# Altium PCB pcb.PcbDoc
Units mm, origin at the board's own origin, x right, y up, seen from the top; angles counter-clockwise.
Board outline 66.48 x 77.37 mm, 2 copper layers (Top Layer, Bottom Layer); 46 components, 42 nets, 221 pads, 768 vias.
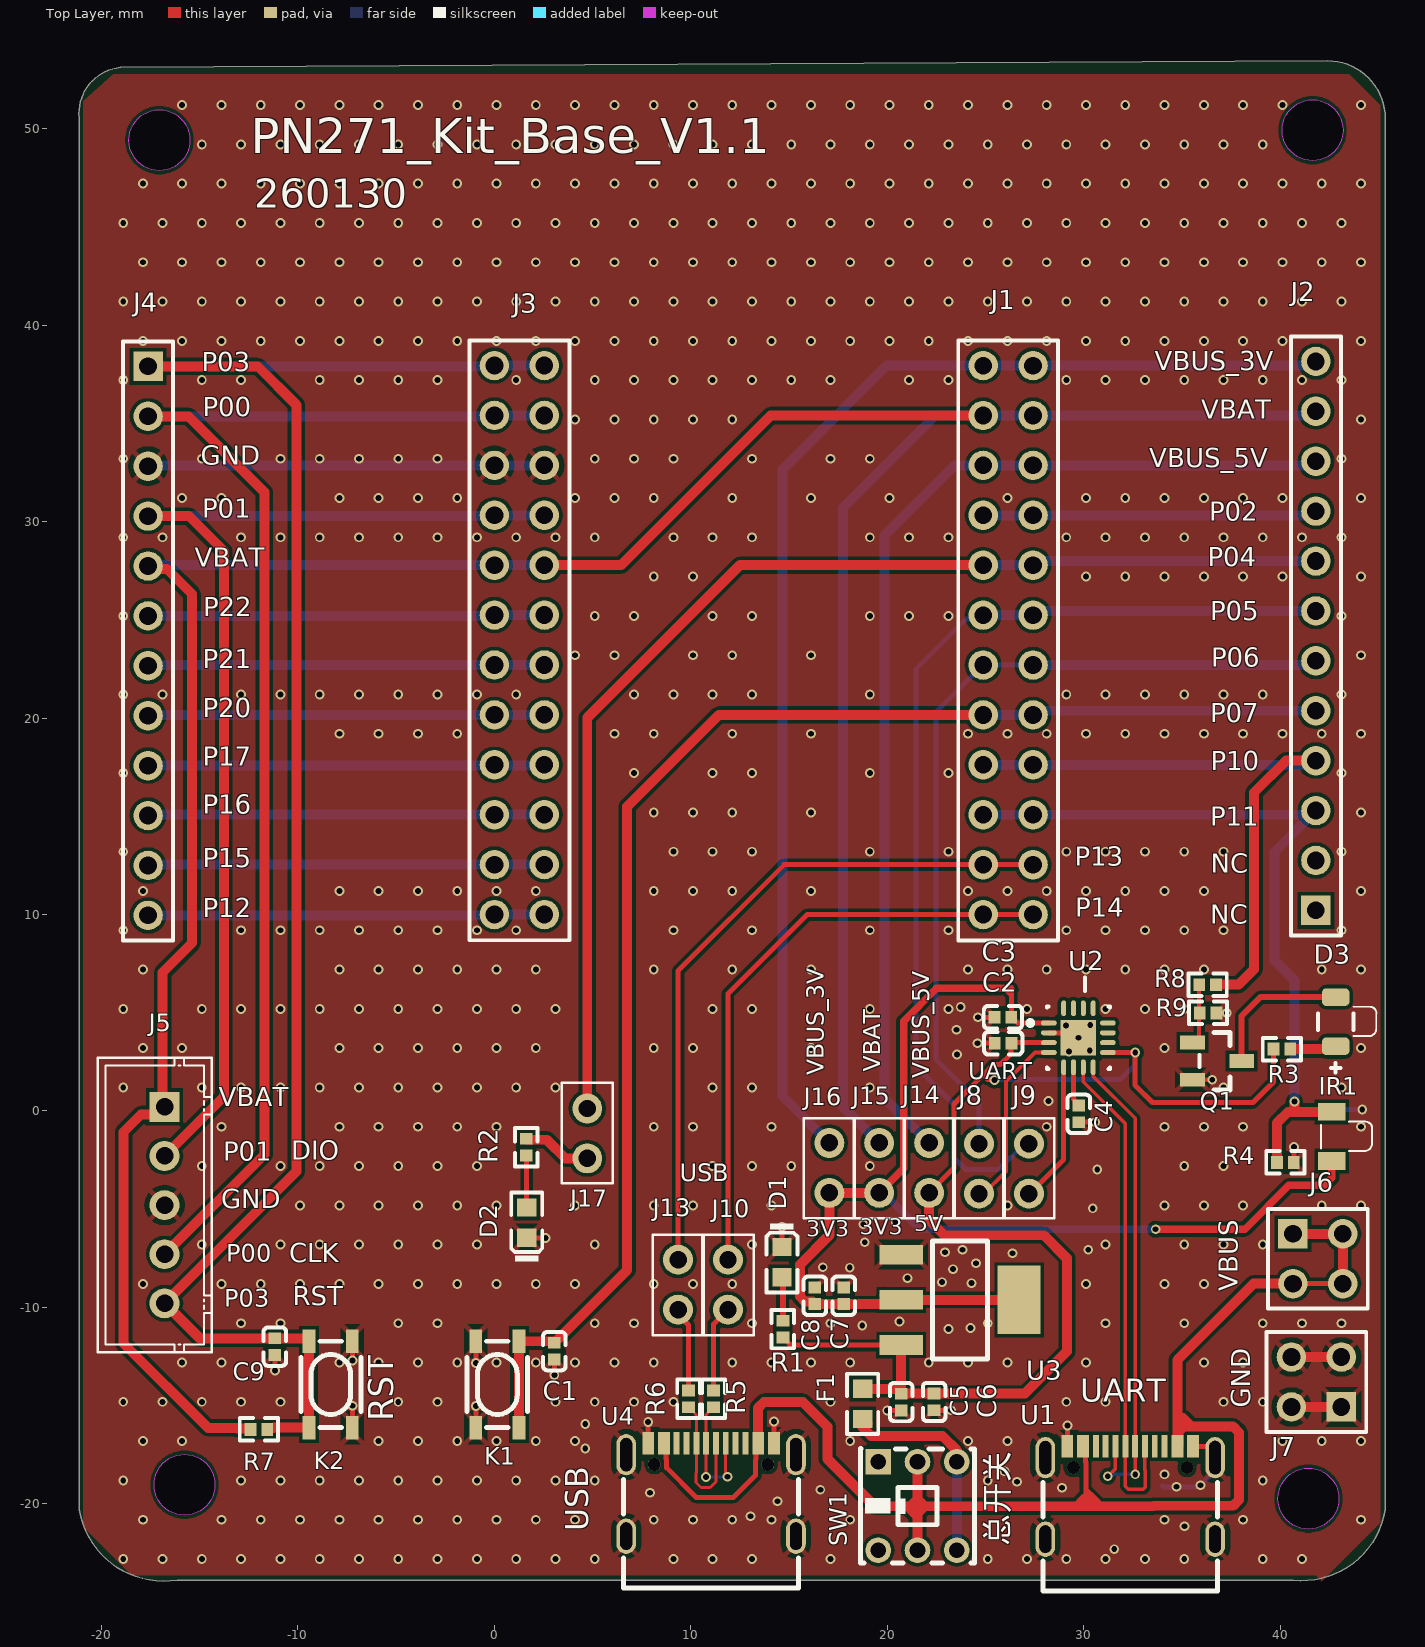
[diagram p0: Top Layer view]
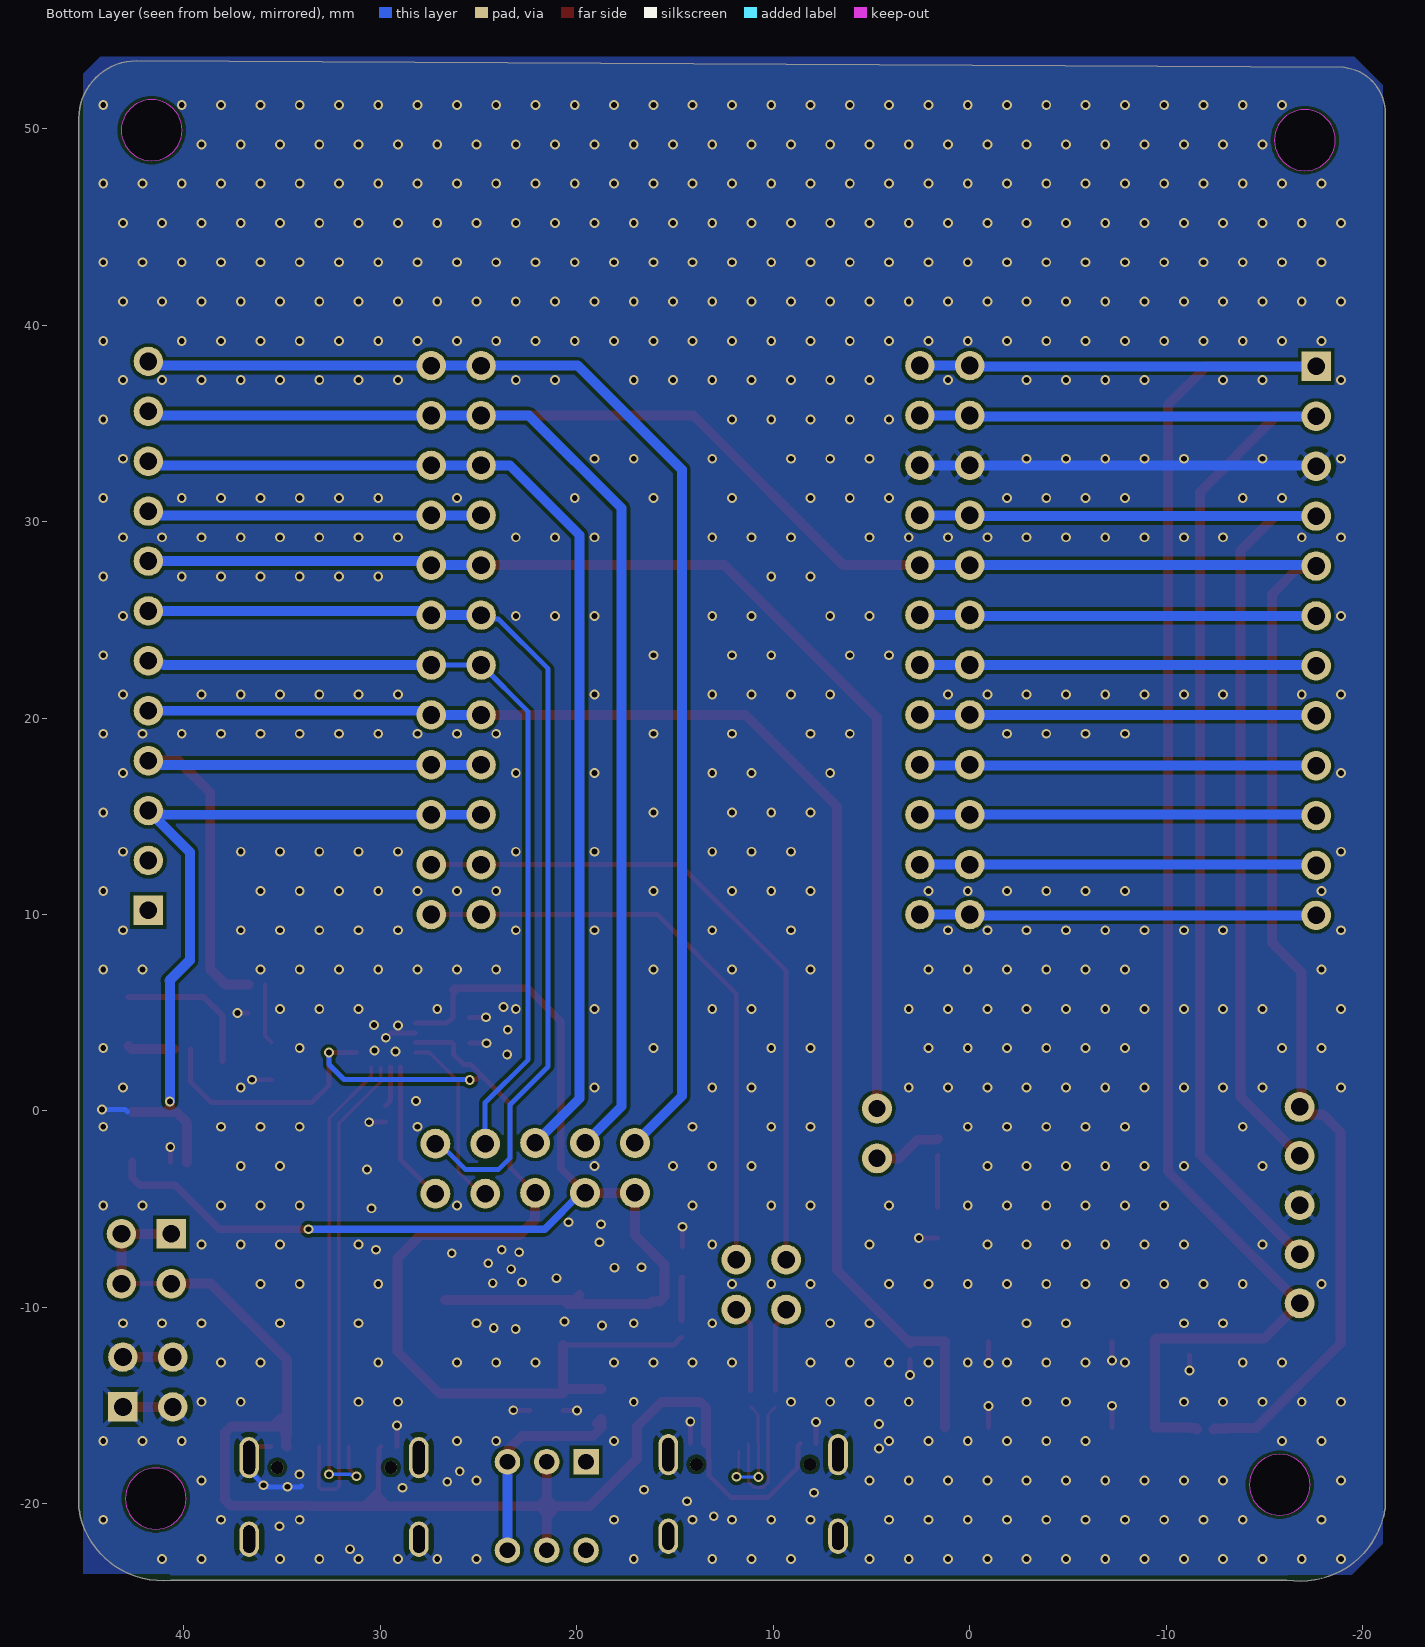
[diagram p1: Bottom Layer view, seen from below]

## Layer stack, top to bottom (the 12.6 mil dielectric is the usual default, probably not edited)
Top Solder: solder mask 0.0102, Solder Resist, Dk 3.5
Top Layer: signal copper 0.0356
Dielectric 1: dielectric 0.32, FR-4, Dk 4.8
Bottom Layer: signal copper 0.0356
Bottom Solder: solder mask 0.0102, Solder Resist, Dk 3.5

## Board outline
-21.13,-20.285 cw(c-20.879,-20.244) -21.133,-20.243 -21.133,-19.254 -21.133,50.559 cw(c-18.809,50.787) -19.051,53.11 cw(c-19.025,52.857) -19.026,53.112 42.417,53.442 cw(c42.418,53.188) 42.418,53.442 cw(c42.418,50.521) 45.339,50.521 cw(c45.085,50.521) 45.339,50.519 45.339,-19.122 45.339,-20.244 cw(c45.085,-20.244) 45.336,-20.283 cw(c41.11,-19.621) 40.667,-23.876 -16.134,-23.876 cw(c-16.827,-19.571)
cut-out: 41.43,-21.279 cw(c41.43,-19.729) 39.88,-19.729 cw(c41.43,-19.729) 41.43,-18.179 cw(c41.43,-19.729) 42.98,-19.729 cw(c41.43,-19.729)
cut-out: 41.64,48.37 cw(c41.64,49.92) 40.09,49.92 cw(c41.64,49.92) 41.64,51.47 cw(c41.64,49.92) 43.19,49.92 cw(c41.64,49.92)
cut-out: -17.053,47.862 cw(c-17.053,49.412) -18.603,49.412 cw(c-17.053,49.412) -17.053,50.962 cw(c-17.053,49.412) -15.503,49.412 cw(c-17.053,49.412)
cut-out: -15.774,-20.575 cw(c-15.774,-19.025) -17.324,-19.025 cw(c-15.774,-19.025) -15.774,-17.475 cw(c-15.774,-19.025) -14.224,-19.025 cw(c-15.774,-19.025)

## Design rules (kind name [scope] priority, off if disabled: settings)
Clearance [All] p1: gap=0.173
HoleSize [All] p1: absolutevalues=TRUE maxlimit=3.81 minlimit=0.025 maxpercent=80.000 minpercent=20.000
MinimumSolderMaskSliver [All] p1: minsoldermaskwidth=0.025
PolygonConnect PolygonConnect_1 [IsVia vs IsPoly] p1: connectstyle=Direct reliefconductorwidth=0.254 reliefentries=4 polygonreliefangle="90 Angle" airgapwidth=0.254
PolygonConnect [All] p2: connectstyle=Relief reliefconductorwidth=0.254 reliefentries=4 polygonreliefangle="45 Angle" airgapwidth=0.254
RoutingVias [All] p1: holewidth=0.3 width=0.5 viastyle="Through Hole" minholewidth=0.3 minwidth=0.5 maxholewidth=0.3 maxwidth=0.5
SilkToSilkClearance [All] p1 off: silktosilkclearance=0.254
SilkToSolderMaskClearance [IsPad] p1 off: minsilkscreentomaskgap=0.254 clearancetoexposedcopper=TRUE
SolderMaskExpansion SolderMaskExpansion_1 [IsVia] p1: expansion=0.102
SolderMaskExpansion [All] p2: expansion=0.102
Width [All] p1: maxlimit=1.27 minlimit=0.152 preferedwidth=0.203 minimp=50.000000 maximp=50.000000 favimp=50.000000
26 further rules are at their usual default settings.

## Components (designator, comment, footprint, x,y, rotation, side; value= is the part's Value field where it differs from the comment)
C1 "100nF / NC" 0402_C 3.048,-12.224 r90 top
C2 "100nF" 0402_C 25.894,3.449 r180 top
C3 "4.7uF" 0402_C 25.88,4.77 r180 top
C4 "100nF" 0402_C 29.743,-0.146 r270 top
C5 "100nF" 0402_C 20.701,-14.815 r90 top
C6 "10uF" 0402_C 22.377,-14.808 r90 top
C7 "100nF" 0402_C 17.78,-9.405 r270 top
C8 "10uF" 0402_C 16.307,-9.405 r270 top
C9 "100nF / NC" 0402_C -11.176,-11.996 r90 top
D1 "红灯 0603" 0603_LED_S1 14.63,-7.696 r270 top
D2 "绿灯 0603" 0603_LED_S1 1.645,-5.686 r90 top
D3 "IR26-51C/L110/TR8" FP-IR26-51C-L110-TR8-MFG 42.816,4.547 r90 top
F1 "" 0603_R 18.745,-14.91 r90 top
IR1 "PT26-51B/TR8" OPTO-SMD_PT26-51B-TR8 42.621,-1.295 r270 top
J1 "Header 2x12" "Header 2X12" 24.875,37.938 r270 top locked
J2 "nc" HDR1X12 41.808,10.211 r90 top
J3 "Header 2x12" "Header 2X12" 0,37.94 r270 top locked
J4 "nc" HDR1X12 -17.628,37.897 r270 top
J5 "SWD" "XH 1x5" -16.789,0.21 r270 top
J6 "Header 2X2" HDR2X2 40.64,-6.248 r270 top
J7 "Header 2X2" HDR2X2 43.104,-15.062 r90 top
J8 "Header 2" "Header 1x2" 24.663,-1.666 r0 top
J9 "Header 2" "Header 1x2" 27.203,-1.666 r0 top
J10 "Header 2" "Header 1x2" 11.887,-10.109 r180 top
J13 "Header 2" "Header 1x2" 9.347,-10.109 r180 top
J14 "Header 2" "Header 1x2" 22.123,-4.166 r180 top
J15 "Header 2" "Header 1x2" 19.583,-4.166 r180 top
J16 "Header 2" "Header 1x2" 17.043,-4.166 r180 top
J17 "Header 2" "Header 1x2" 4.724,0.127 r0 top
K1 "K2-1808GN-A4SW-04" KEY-SMD_4P-L4.2-W3.2-P2.20-LS5.1-TL 0.152,-13.919 r270 top
K2 "K2-1808GN-A4SW-04" KEY-SMD_4P-L4.2-W3.2-P2.20-LS5.1-TL -8.331,-13.919 r90 top
Q1 "SS8050 Y1" SOT-23(SOT-23-3) 36.779,2.54 r180 top
R1 "1KΩ" 0402_R 14.681,-11.1 r90 top
R2 "1KΩ" 0402_R 1.619,-1.843 r270 top
R3 "100Ω" 0402_R 40.081,3.15 r180 top
R4 "300Ω" 0402_R 40.259,-2.616 r180 top
R5 "0Ω" 0402_R 11.151,-14.649 r270 top
R6 "0Ω" 0402_R 9.881,-14.649 r270 top
R7 "NC" 0402_R -11.989,-16.205 r180 top
R8 "300Ω" 0402_R 36.297,6.426 r180 top
R9 "10KΩ" 0402_R 36.32,4.994 r180 top
SW1 "K8-5851E-L1" SW-TH_6P-L5.8-W5.8-P2.00-LS4.5-TL_K8-5851E-L1 21.533,-20.106 r0 top
U1 "USB_Type-C(Seat-16P)" USB-C-SMD_TYPE-C16PIN 32.36,-19.431 r0 top
U2 "CH343P" QFN16 29.723,3.728 r0 top
U3 "AMS1117-3.3" SOT-223 23.701,-9.613 r180 top
U4 "USB_Type-C(Seat-16P)" USB-C-SMD_TYPE-C16PIN 11.026,-19.279 r0 top

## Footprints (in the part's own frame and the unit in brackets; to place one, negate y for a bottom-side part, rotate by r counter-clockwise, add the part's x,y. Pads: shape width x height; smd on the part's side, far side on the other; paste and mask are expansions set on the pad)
0402_C [mm]
  rect 0.6x0.65 smd mask+0.051: 1(-0.425,0) 2(0.425,0)
  silkscreen extent -0.97,-0.58 0.97,0.58, body extent -0.48,-0.3 0.52,0.3, height 0.2
0402_R [mm]
  rect 0.6x0.65 smd mask+0.051: 1(-0.425,0) 2(0.425,0)
  silkscreen extent -0.97,-0.58 0.97,0.58, body extent -0.57,-0.27 0.58,0.28, height 0.41
0603_LED_S1 [mm]
  rect 0.93x0.98 smd: A(0.77,0) K(-0.77,0)
  silkscreen extent -1.97,-0.79 1.54,0.79, body extent -0.8,-0.4 0.8,0.4, height 0.6
0603_R [mm]
  rect 0.93x0.98 smd: 1(-0.77,0) 2(0.77,0)
  silkscreen extent -1.53,-0.79 1.54,0.79, body extent -0.85,-0.4 0.85,0.4, height 0.56
FP-IR26-51C-L110-TR8-MFG [mm]
  rrect50% 0.9x1.4 smd paste+0 mask+0: 1(-1.25,0) 2(1.25,0)
  silkscreen extent -2.6,-0.9 0.43,0.9, body extent -1.8,-1 1.8,1, height 0.25
HDR1X12 [mm] "Connector; Header; 12 Position"
  rect 1.5x1.5 hole 0.9: 1(0,0)
  round 1.5 hole 0.9: 2(2.54,0) 3(5.08,0) 4(7.62,0) 5(10.16,0) 6(12.7,0) 7(15.24,0) 8(17.78,0) 9(20.32,0) 10(22.86,0) 11(25.4,0) 12(27.94,0)
  silkscreen extent -1.27,-1.27 29.21,1.27
HDR2X2 [mm] "Connector; Header; 2x2 Position"
  rect 1.5x1.5 hole 0.9: 1(0,0)
  round 1.5 hole 0.9: 2(0,2.54) 3(2.54,0) 4(2.54,2.54)
  silkscreen extent -1.27,-1.27 3.81,3.81
"Header 1x2" [mil] "Header 1x2,2.54mm"
  round 60 hole 35: 1(0,0) 2(0,-100)
  silkscreen extent -51,-150 51,51, body extent -50,-150 50,50, height 335
"Header 2X12" [mm] "Connector; Header; 12x2 Position"
  round 1.5 hole 0.9: 1(0,0) 2(0,2.54) 3(2.54,0) 4(2.54,2.54) 5(5.08,0) 6(5.08,2.54) 7(7.62,0) 8(7.62,2.54) 9(10.16,0) 10(10.16,2.54) 11(12.7,0) 12(12.7,2.54) 13(15.24,0) 14(15.24,2.54) 15(17.78,0) 16(17.78,2.54) 17(20.32,0) 18(20.32,2.54) 19(22.86,0) 20(22.86,2.54) 21(25.4,0) 22(25.4,2.54) 23(27.94,0) 24(27.94,2.54)
  silkscreen extent -1.27,-1.27 29.25,3.81, body extent -1.27,-1.27 29.21,3.81, height 8.5
KEY-SMD_4P-L4.2-W3.2-P2.20-LS5.1-TL [mm]
  rect 1.2x0.65 smd: 1(-2.2,1.1) 2(2.2,1.1) 3(-2.2,-1.1) 4(2.2,-1.1)
  silkscreen extent -2.2,-1.55 2.2,1.52
OPTO-SMD_PT26-51B-TR8 [mm]
  rect 0.9x1.4 smd paste+0 mask+0.05: 1(-1.25,0) 2(1.25,0)
  silkscreen extent -0.76,-0.55 0.74,2.05
QFN16 [mm]
  oval 0.8x0.25 smd: 1(-1.5,0.75) 2(-1.5,0.25) 3(-1.5,-0.25) 4(-1.5,-0.75) 9(1.5,-0.75) 10(1.5,-0.25) 11(1.5,0.25) 12(1.5,0.75)
  oval 0.25x0.8 smd: 5(-0.75,-1.5) 6(-0.25,-1.5) 7(0.25,-1.5) 8(0.75,-1.5) 13(0.75,1.5) 14(0.25,1.5) 15(-0.25,1.5) 16(-0.75,1.5)
  rect 1.8x1.8 smd: 17(0,0)
  silkscreen extent -2.57,-1.6 1.6,1.6, body extent -1.58,-1.58 1.58,1.58, height 1
SOT-23(SOT-23-3) [mm]
  rect 1.25x0.7 smd: 1(1.25,-0.95) 2(1.25,0.95) 3(-1.25,0)
  silkscreen extent -0.65,-1.46 0.9,1.46, body extent -1.5,-1.5 1.5,1.5, height 1.3
SOT-223 [mm]
  rect 2.2x1 smd: 1(3,-2.3) 2(3,0) 3(3,2.3)
  rect 2.2x3.5 smd: 2(-3,0)
  silkscreen extent -1.4,-3 1.4,3, body extent -3.49,-3.24 3.49,3.24, height 1.64
SW-TH_6P-L5.8-W5.8-P2.00-LS4.5-TL_K8-5851E-L1 [mm]
  rect 1.3x1.3 hole 0.8 paste+0 mask+0.05: 1(-2,2.25)
  round 1.3 hole 0.8 paste+0 mask+0.05: 2(0,2.25) 3(2,2.25) 4(-2,-2.25) 5(0,-2.25) 6(2,-2.25)
  silkscreen extent -2.9,-2.9 2.9,2.92
USB-C-SMD_TYPE-C16PIN [mm]
  oval 1x2.1 hole 0.6 slot 1.7 at 90 deg: 1(-4.32,1.787) 2(4.32,1.787)
  oval 1x1.8 hole 0.6 slot 1.4 at 90 deg: 3(-4.32,-2.362) 4(4.32,-2.362)
  rect 0.6x1.15 smd: A1/B12(-3.2,2.362) A4/B9(-2.4,2.362) A9/B4(2.4,2.362) A12/B1(3.2,2.362)
  rect 0.3x1.15 smd: A5(-1.25,2.362) A6(-0.25,2.362) A7(0.25,2.362) A8(-1.75,2.362) B5(1.75,2.362) B6(0.75,2.362) B7(-0.75,2.362) B8(1.25,2.362)
  round 0.65 hole 0.65 unplated: ""(-2.89,1.288) ""(2.89,1.288)
  silkscreen extent -4.45,-5 4.45,0.52, body extent -4.47,-5 4.47,2.9, height 3.2
"XH 1x5" [mil] "XH 1x5,2.5mm"
  rect 60x60 / inner round 60 / far side round 60 hole 35: 1(0,0)
  round 60 hole 35: 2(98.43,0) 3(196.85,0) 4(295.28,0) 5(393.7,0)
  silkscreen extent -98,-134 492,94

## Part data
C1 C2 C4 C5 C7 C9: library part "0402 100nF (104) 10% 16V", "贴片电容"
C3: library part "0402 4.7uF (475) 20% 10V", "贴片电容"
C6 C8: library part "0402 10uF (106) 20% 6.3V", "贴片电容"
D1: library part "0603 红灯", "发光二极管"
D2: library part "0603 绿灯", "发光二极管"
D3: "EMITTER IR 940NM 65MA SMD"
F1: library part Res1, "Resistor"
J1 J3: "Header 2x11,2.54mm"
J2 J4: library part "Header 12", "Header, 12-Pin"
J5: library part "Header 1x5", "Header 1x5,2.54mm"
J6 J7: "Header, 2-Pin, Dual row"
J8 J9 J10 J13 J14 J15 J16 J17: library part SW-SPST, "Header, 2-Pin"
Q1: library part "SOT-23 SS8050 Y1", "三极管"
R1 R2 R7: library part "0402 1KΩ (1001) 1%", "贴片电阻"
R3 R4 R8: library part "0402 300Ω (3000) 1%", "贴片电阻"
R5 R6: library part "0402 0Ω (0R0) 1%", "贴片电阻"
R9: library part "0402 10KΩ (1002) 1%", "贴片电阻"
U2: "USB 转高速串口芯片"
U3: library part "SOT-223 AMS1117-3.3", "低压差线性稳压(LDO)"

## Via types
v1: diameter 0.5, hole 0.3, Top Layer to Bottom Layer, tented both sides, 768 vias

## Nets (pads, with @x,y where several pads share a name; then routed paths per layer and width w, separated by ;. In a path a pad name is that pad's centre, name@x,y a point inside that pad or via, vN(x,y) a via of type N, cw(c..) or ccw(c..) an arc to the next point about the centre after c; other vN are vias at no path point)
3V3_1: C3.1 C7.2 C8.2 IR1.2 J15.1 J16.1 U2.1 U3.2 | length 65.9
  Top Layer w0.254: 25.806,6.243 25.955,6.243 26.305,5.893 ; 26.305,6.181 26.305,5.893 ; U2.1 26.627,4.478 26.534,4.572 26.478,4.572 26.305,4.745 C3.1 26.305,5.893
  Top Layer w0.381: J15.1 20.828,-2.921 20.828,4.572 22.499,6.243 25.806,6.243 ; 25.955,6.243 26.244,6.243 26.305,6.181 ; v1(33.655,-6.02) 38.202,-6.02 40.437,-3.785 42.24,-3.785 42.621,-3.404 IR1.2
  Top Layer w0.508: J15.1 J16.1 17.043,-6.325 15.547,-7.821 15.547,-9.449 15.805,-9.707 16.184,-9.707 C8.2 C7.2 20.484,-9.83 U3.2@20.701,-9.613 ; U3.2@19.855,-9.367 20.101,-9.613 U3.2@20.701,-9.613 ; U3.2@26.701,-9.613 U3.2@20.701,-9.613
  Bottom Layer w0.381: J15.1 19.79,-4.166 21.644,-6.02 v1(33.655,-6.02)
5V_1: C2.1 C5.2 C6.2 F1.2 J14.1 R1.1 R3.2 U2.3 U2.9 U3.3 | length 66.5
  Top Layer w0.254: R1.1 14.706,-11.525 14.879,-11.698 14.879,-11.723 15.069,-11.913 U3.3 ; J14.1 23.393,-2.896 23.393,0.356 24.879,1.841 ; v1(25.451,1.575) 25.411,1.615 25.106,1.615 24.879,1.841 ; U2.3 26.348,3.478 C2.1 26.285,3.415 26.285,2.892 25.756,2.362 25.4,2.362 24.879,1.841 ; U2.9 32.607,2.978 32.607,1.315 33.491,0.432 38.608,0.432 39.656,1.48 R3.2
  Top Layer w0.508: F1.2 C5.2@20.451,-14.14 ; U3.3 C5.2 20.708,-14.383 C6.2 26.993,-14.383 29.134,-12.243 29.134,-7.493 27.965,-6.325 22.911,-6.325 22.708,-6.122 22.123,-5.537 J14.1
  Bottom Layer w0.254: v1(25.451,1.575) 25.476,1.6 31.852,1.6 32.614,2.362 v1(32.614,2.972)
DM_1: R6.2 U4.A7 U4.B7 | length 7.2
  Top Layer w0.152: R6.2 9.906,-15.074 10.129,-15.298 10.129,-15.323 10.276,-15.469 U4.B7 10.276,-18.41 10.261,-18.424 10.261,-18.912 10.26,-18.913 10.508,-19.16 10.979,-19.16 11.276,-18.864 U4.A7
DP_1: R5.2 U4.A6 U4.B6 | length 6.2
  Top Layer w0.152: v1(10.76,-18.631) U4.A6@10.76,-16.916 ; U4.A6 10.776,-15.449 10.902,-15.323 10.902,-15.298 11.126,-15.074 R5.2 ; U4.B6@11.76,-17.323 11.76,-18.416 11.868,-18.524 v1(11.868,-18.618)
  Bottom Layer w0.152: v1(10.76,-18.631) 11.855,-18.631 v1(11.868,-18.618)
GND: C1.1 C2.2 C3.2 C4.2 C5.1 C6.1 C7.1 C8.1 C9.1 D1.K D2.K J3.5 J3.6 J4.3 J5.3 J7.1 J7.2 J7.3 J7.4 K1.3 K1.4 K2.3 K2.4 Q1.2 R4.1 R9.1 U1.1 U1.2 U1.3 U1.4 U1.A1/B12 U1.A12/B1 U2.2 U2.17 U3.1 U4.1 U4.2 U4.3 U4.4 U4.A1/B12 U4.A12/B1 | length 51
  Top Layer w0.254: v1(-11.176,-13.208) C9.1 ; K2.3 v1(-7.231,-15.004) ; v1(-7.231,-12.692) K2.4 ; K1.4 v1(-0.948,-15.019) ; v1(-0.948,-12.819) K1.3 ; D2.K v1(2.596,-6.456) ; v1(3.048,-13.437) C1.1 ; U4.A1/B12 v1(7.826,-15.822) ; U4.A12/B1 v1(14.226,-15.797) ; D1.K v1(14.63,-5.893) ; v1(19.99,-15.24) C5.1 ; C6.1 v1(23.234,-15.233) ; v1(24.593,3.449) C2.2 ; v1(24.616,4.77) C3.2 ; U2.2 29.473,3.978 v1(29.723,3.728) ; U1.A1/B12 v1(29.16,-16.002) ; C4.2 v1(30.57,-0.571) ; Q1.2 v1(36.535,1.59) ; U1.A12/B1 36.335,-17.069 36.68,-17.413 U1.2 ; R9.1 v1(37.272,4.994) ; R4.1 40.691,-2.609 v1(40.691,-1.829)
  Top Layer w0.508: J7.2 J7.1 ; J7.4 J7.3
  Bottom Layer w0.254: 34.011,-19.075 34.061,-19.126 v1(34.722,-19.126) 35.691,-19.126 35.72,-19.097 35.894,-19.097 v1(35.941,-19.05) 36.68,-18.311 U1.2 ; 42.871,-0.045 42.993,0.076 v1(44.171,0.076)
  Bottom Layer w0.508: J4.3 -17.584,32.86 J3.5 J3.6
  other v1: -18.893,-22.802 -16.893,-22.802 -14.893,-22.802 -12.893,-22.802 -10.893,-22.802 -8.893,-22.802 -6.893,-22.802 -4.893,-22.802 -2.893,-22.802 -0.893,-22.802 1.107,-22.802 3.107,-22.802 5.107,-22.802 9.107,-22.802 11.107,-22.802 13.107,-22.802 17.107,-22.802 25.107,-22.802 27.107,-22.802 29.107,-22.802 31.107,-22.802 33.107,-22.802 35.107,-22.802 39.107,-22.802 41.107,-22.802 31.547,-22.301 35.128,-21.133 -17.893,-20.802 -13.893,-20.802 -11.893,-20.802 -9.893,-20.802 -7.893,-20.802 -5.893,-20.802 -3.893,-20.802 -1.893,-20.802 0.107,-20.802 2.107,-20.802 4.107,-20.802 8.107,-20.802 10.107,-20.802 12.107,-20.802 14.107,-20.802 18.107,-20.802 34.107,-20.802 38.107,-20.802 44.107,-20.802 13.03,-20.625 14.402,-19.863 7.925,-19.431 16.586,-19.279 28.88,-19.177 26.594,-18.872 -18.893,-18.802 -12.893,-18.802 -10.893,-18.802 -8.893,-18.802 -6.893,-18.802 -4.893,-18.802 -2.893,-18.802 -0.893,-18.802 1.107,-18.802 3.107,-18.802 5.107,-18.802 25.107,-18.802 39.107,-18.802 34.112,-18.491 25.959,-18.339 4.623,-17.17 -17.893,-16.802 -15.893,-16.802 -5.893,-16.802 -3.893,-16.802 -1.893,-16.802 0.107,-16.802 2.107,-16.802 4.107,-16.802 18.107,-16.802 24.107,-16.802 26.107,-16.802 40.107,-16.802 42.107,-16.802 44.107,-16.802 4.623,-15.926 -18.893,-14.802 -16.893,-14.802 -14.893,-14.802 -12.893,-14.802 -10.893,-14.802 -4.893,-14.802 -2.893,-14.802 3.107,-14.802 5.107,-14.802 7.107,-14.802 9.107,-14.802 17.107,-14.802 29.107,-14.802 31.107,-14.802 37.107,-14.802 39.107,-14.802 -15.893,-12.802 -13.893,-12.802 -7.893,-12.802 -5.893,-12.802 -3.893,-12.802 -1.893,-12.802 0.107,-12.802 2.107,-12.802 4.107,-12.802 6.107,-12.802 8.107,-12.802 12.107,-12.802 14.107,-12.802 16.107,-12.802 18.107,-12.802 22.107,-12.802 24.107,-12.802 26.107,-12.802 30.107,-12.802 36.107,-12.802 38.107,-12.802 23.114,-11.1 24.232,-11.049 18.72,-10.922 -12.893,-10.802 -10.893,-10.802 -4.893,-10.802 -2.893,-10.802 5.107,-10.802 7.107,-10.802 13.107,-10.802 17.107,-10.802 25.107,-10.802 31.107,-10.802 35.107,-10.802 39.107,-10.802 41.107,-10.802 43.107,-10.802 20.625,-10.719 -17.893,-8.802 -13.893,-8.802 -11.893,-8.802 -9.893,-8.802 -7.893,-8.802 -5.893,-8.802 -3.893,-8.802 -1.893,-8.802 0.107,-8.802 2.107,-8.802 4.107,-8.802 8.107,-8.802 10.107,-8.802 12.107,-8.802 30.107,-8.802 34.107,-8.802 36.107,-8.802 24.282,-8.763 22.784,-8.712 21.031,-8.509 23.343,-8.052 18.085,-7.976 16.713,-7.95 24.511,-7.747 26.365,-7.239 22.936,-7.188 23.825,-7.061 30.226,-7.061 -14.893,-6.802 -10.893,-6.802 -8.893,-6.802 -6.893,-6.802 -4.893,-6.802 -2.893,-6.802 -0.893,-6.802 5.107,-6.802 13.107,-6.802 31.107,-6.802 35.107,-6.802 37.107,-6.802 39.107,-6.802 18.847,-6.68 18.771,-5.766 20.422,-5.664 30.455,-4.953 -9.893,-4.802 -7.893,-4.802 -5.893,-4.802 -3.893,-4.802 -1.893,-4.802 0.107,-4.802 4.107,-4.802 8.107,-4.802 10.107,-4.802 14.107,-4.802 26.107,-4.802 34.107,-4.802 36.107,-4.802 38.107,-4.802 42.107,-4.802 44.107,-4.802 30.683,-2.972 -14.893,-2.802 -10.893,-2.802 -8.893,-2.802 -6.893,-2.802 -4.893,-2.802 -2.893,-2.802 -0.893,-2.802 11.107,-2.802 13.107,-2.802 15.107,-2.802 19.107,-2.802 35.107,-2.802 37.107,-2.802 -13.893,-0.802 -7.893,-0.802 -5.893,-0.802 -3.893,-0.802 -1.893,-0.802 0.107,-0.802 8.107,-0.802 10.107,-0.802 14.107,-0.802 28.107,-0.802 34.107,-0.802 36.107,-0.802 38.107,-0.802 44.107,-0.802 28.194,0.508 -18.893,1.198 -14.893,1.198 -12.893,1.198 -10.893,1.198 -8.893,1.198 -6.893,1.198 -4.893,1.198 -2.893,1.198 -0.893,1.198 1.107,1.198 3.107,1.198 11.107,1.198 13.107,1.198 19.107,1.198 37.107,1.198 43.107,1.198 23.546,2.87 29.235,3.023 30.302,3.073 -17.893,3.198 -15.893,3.198 -7.893,3.198 -5.893,3.198 -3.893,3.198 -1.893,3.198 0.107,3.198 2.107,3.198 8.107,3.198 10.107,3.198 16.107,3.198 34.107,3.198 44.107,3.198 23.519,4.137 29.098,4.353 30.328,4.369 -18.893,5.198 -14.893,5.198 -12.893,5.198 -10.893,5.198 -8.893,5.198 -6.893,5.198 -4.893,5.198 -2.893,5.198 -0.893,5.198 1.107,5.198 3.107,5.198 11.107,5.198 13.107,5.198 19.107,5.198 23.107,5.198 27.107,5.198 31.107,5.198 33.107,5.198 35.107,5.198 23.73,5.297 -17.893,7.198 -7.893,7.198 -5.893,7.198 -3.893,7.198 -1.893,7.198 0.107,7.198 2.107,7.198 8.107,7.198 12.107,7.198 16.107,7.198 24.107,7.198 26.107,7.198 28.107,7.198 30.107,7.198 32.107,7.198 34.107,7.198 36.107,7.198 42.107,7.198 44.107,7.198 -18.893,9.198 -12.893,9.198 -10.893,9.198 -8.893,9.198 -6.893,9.198 -4.893,9.198 -2.893,9.198 -0.893,9.198 1.107,9.198 9.107,9.198 13.107,9.198 19.107,9.198 23.107,9.198 29.107,9.198 31.107,9.198 33.107,9.198 35.107,9.198 37.107,9.198 43.107,9.198 -17.893,11.198 -7.893,11.198 -5.893,11.198 -3.893,11.198 -1.893,11.198 0.107,11.198 2.107,11.198 8.107,11.198 10.107,11.198 12.107,11.198 16.107,11.198 24.107,11.198 26.107,11.198 28.107,11.198 30.107,11.198 32.107,11.198 34.107,11.198 36.107,11.198 44.107,11.198 -18.893,13.198 9.107,13.198 11.107,13.198 13.107,13.198 19.107,13.198 23.107,13.198 29.107,13.198 31.107,13.198 33.107,13.198 35.107,13.198 37.107,13.198 43.107,13.198 8.107,15.198 10.107,15.198 12.107,15.198 16.107,15.198 44.107,15.198 -18.893,17.198 7.107,17.198 11.107,17.198 13.107,17.198 19.107,17.198 23.107,17.198 43.107,17.198 -7.893,19.198 -5.893,19.198 -3.893,19.198 -1.893,19.198 6.107,19.198 8.107,19.198 12.107,19.198 16.107,19.198 24.107,19.198 26.107,19.198 28.107,19.198 30.107,19.198 32.107,19.198 34.107,19.198 36.107,19.198 38.107,19.198 40.107,19.198 42.107,19.198 44.107,19.198 -18.893,21.198 -16.893,21.198 -12.893,21.198 -10.893,21.198 -8.893,21.198 -6.893,21.198 -4.893,21.198 -2.893,21.198 -0.893,21.198 1.107,21.198 7.107,21.198 9.107,21.198 11.107,21.198 13.107,21.198 19.107,21.198 29.107,21.198 31.107,21.198 33.107,21.198 35.107,21.198 37.107,21.198 39.107,21.198 43.107,21.198 4.107,23.198 6.107,23.198 10.107,23.198 12.107,23.198 16.107,23.198 44.107,23.198 -18.893,25.198 5.107,25.198 7.107,25.198 11.107,25.198 13.107,25.198 19.107,25.198 21.107,25.198 23.107,25.198 43.107,25.198 8.107,27.198 10.107,27.198 30.107,27.198 32.107,27.198 34.107,27.198 36.107,27.198 38.107,27.198 40.107,27.198 44.107,27.198 -18.893,29.198 -16.893,29.198 -12.893,29.198 -10.893,29.198 -8.893,29.198 -6.893,29.198 -4.893,29.198 -2.893,29.198 -0.893,29.198 1.107,29.198 3.107,29.198 5.107,29.198 9.107,29.198 11.107,29.198 13.107,29.198 19.107,29.198 21.107,29.198 23.107,29.198 29.107,29.198 31.107,29.198 33.107,29.198 35.107,29.198 37.107,29.198 39.107,29.198 41.107,29.198 43.107,29.198 -15.893,31.198 -13.893,31.198 -7.893,31.198 -5.893,31.198 -3.893,31.198 -1.893,31.198 4.107,31.198 6.107,31.198 8.107,31.198 12.107,31.198 16.107,31.198 20.107,31.198 26.107,31.198 30.107,31.198 32.107,31.198 34.107,31.198 36.107,31.198 38.107,31.198 40.107,31.198 44.107,31.198 -18.893,33.198 -14.893,33.198 -10.893,33.198 -8.893,33.198 -6.893,33.198 -4.893,33.198 -2.893,33.198 5.107,33.198 7.107,33.198 9.107,33.198 13.107,33.198 17.107,33.198 19.107,33.198 43.107,33.198 4.107,35.198 6.107,35.198 8.107,35.198 10.107,35.198 12.107,35.198 44.107,35.198 -18.893,37.198 -14.893,37.198 -12.893,37.198 -8.893,37.198 -6.893,37.198 -4.893,37.198 -2.893,37.198 1.107,37.198 5.107,37.198 7.107,37.198 9.107,37.198 11.107,37.198 13.107,37.198 15.107,37.198 17.107,37.198 21.107,37.198 23.107,37.198 29.107,37.198 31.107,37.198 33.107,37.198 35.107,37.198 37.107,37.198 39.107,37.198 41.107,37.198 43.107,37.198 -17.893,39.198 -15.893,39.198 -13.893,39.198 -11.893,39.198 -9.893,39.198 -7.893,39.198 -5.893,39.198 -3.893,39.198 -1.893,39.198 0.107,39.198 2.107,39.198 4.107,39.198 6.107,39.198 8.107,39.198 10.107,39.198 12.107,39.198 14.107,39.198 16.107,39.198 18.107,39.198 20.107,39.198 22.107,39.198 24.107,39.198 26.107,39.198 28.107,39.198 30.107,39.198 32.107,39.198 34.107,39.198 36.107,39.198 38.107,39.198 40.107,39.198 44.107,39.198 -18.893,41.198 -16.893,41.198 -14.893,41.198 -12.893,41.198 -10.893,41.198 -8.893,41.198 -6.893,41.198 -4.893,41.198 -2.893,41.198 -0.893,41.198 1.107,41.198 3.107,41.198 5.107,41.198 7.107,41.198 9.107,41.198 11.107,41.198 13.107,41.198 15.107,41.198 17.107,41.198 19.107,41.198 21.107,41.198 23.107,41.198 25.107,41.198 27.107,41.198 29.107,41.198 31.107,41.198 33.107,41.198 35.107,41.198 37.107,41.198 39.107,41.198 41.107,41.198 43.107,41.198 -17.893,43.198 -15.893,43.198 -13.893,43.198 -11.893,43.198 -9.893,43.198 -7.893,43.198 -5.893,43.198 -3.893,43.198 -1.893,43.198 0.107,43.198 2.107,43.198 4.107,43.198 6.107,43.198 8.107,43.198 10.107,43.198 12.107,43.198 14.107,43.198 16.107,43.198 18.107,43.198 20.107,43.198 22.107,43.198 24.107,43.198 26.107,43.198 28.107,43.198 30.107,43.198 32.107,43.198 34.107,43.198 36.107,43.198 38.107,43.198 40.107,43.198 42.107,43.198 44.107,43.198 -18.893,45.198 -16.893,45.198 -14.893,45.198 -12.893,45.198 -10.893,45.198 -8.893,45.198 -6.893,45.198 -4.893,45.198 -2.893,45.198 -0.893,45.198 1.107,45.198 3.107,45.198 5.107,45.198 7.107,45.198 9.107,45.198 11.107,45.198 13.107,45.198 15.107,45.198 17.107,45.198 19.107,45.198 21.107,45.198 23.107,45.198 25.107,45.198 27.107,45.198 29.107,45.198 31.107,45.198 33.107,45.198 35.107,45.198 37.107,45.198 39.107,45.198 41.107,45.198 43.107,45.198 -17.893,47.198 -15.893,47.198 -13.893,47.198 -11.893,47.198 -9.893,47.198 -7.893,47.198 -5.893,47.198 -3.893,47.198 -1.893,47.198 0.107,47.198 2.107,47.198 4.107,47.198 6.107,47.198 8.107,47.198 10.107,47.198 12.107,47.198 14.107,47.198 16.107,47.198 18.107,47.198 20.107,47.198 22.107,47.198 24.107,47.198 26.107,47.198 28.107,47.198 30.107,47.198 32.107,47.198 34.107,47.198 36.107,47.198 38.107,47.198 40.107,47.198 42.107,47.198 44.107,47.198 -14.893,49.198 -12.893,49.198 -10.893,49.198 -8.893,49.198 -6.893,49.198 -4.893,49.198 -2.893,49.198 -0.893,49.198 1.107,49.198 3.107,49.198 5.107,49.198 7.107,49.198 9.107,49.198 11.107,49.198 13.107,49.198 15.107,49.198 17.107,49.198 19.107,49.198 21.107,49.198 23.107,49.198 25.107,49.198 27.107,49.198 29.107,49.198 31.107,49.198 33.107,49.198 35.107,49.198 37.107,49.198 39.107,49.198 -15.893,51.198 -13.893,51.198 -11.893,51.198 -9.893,51.198 -7.893,51.198 -5.893,51.198 -3.893,51.198 -1.893,51.198 0.107,51.198 2.107,51.198 4.107,51.198 6.107,51.198 8.107,51.198 10.107,51.198 12.107,51.198 14.107,51.198 16.107,51.198 18.107,51.198 20.107,51.198 22.107,51.198 24.107,51.198 26.107,51.198 28.107,51.198 30.107,51.198 32.107,51.198 34.107,51.198 36.107,51.198 38.107,51.198 40.107,51.198 44.107,51.198
NetC4_1: C4.1 U2.6 | length 2.1
  Top Layer w0.254: U2.6 29.473,0.601 29.545,0.528 29.545,0.452 29.718,0.279 C4.1
NetD1_A: D1.A R1.2 | length 2.2
  Top Layer w0.305: D1.A 14.681,-8.517 R1.2
NetD2_A: D2.A R2.2 | length 2.7
  Top Layer w0.254: R2.2 1.645,-2.293 D2.A
NetD3_1: D3.1 R3.1 | length 2.4
  Top Layer w0.508: R3.1 42.669,3.15 D3.1
NetD3_2: D3.2 Q1.3 | length 7.5
  Top Layer w0.3: Q1.3 38.029,4.841 38.985,5.797 D3.2
NetF1_1: F1.1 SW1.3 SW1.6 | length 11.1
  Top Layer w0.508: F1.1@18.981,-15.916 18.981,-15.891 18.77,-15.68 F1.1 18.745,-16.104 19.177,-16.535 22.799,-16.535 23.533,-17.269 SW1.3
  Bottom Layer w0.508: SW1.6 SW1.3
NetJ8_2: J8.2 U2.4 | length 9.2
  Top Layer w0.191: J8.2@24.663,-4.242 24.867,-4.242 26.035,-3.073 26.035,1.499 27.515,2.978 U2.4
NetJ9_2: J9.2 U2.5 | length 7.2
  Top Layer w0.254: J9.2@27.203,-4.242 28.973,-2.473 U2.5
NetJ10_1: J10.1 R5.1 | length 4.4
  Top Layer w0.254: R5.1 11.151,-10.846 J10.1
NetJ13_1: J13.1 R6.1 | length 4.3
  Top Layer w0.254: J13.1 9.347,-10.36 9.881,-10.893 R6.1
NetJ17_2: J17.2 R2.1 | length 3.5
  Top Layer w0.508: R2.1 1.665,-1.464 2.666,-1.464 3.615,-2.413 J17.2
NetQ1_1: Q1.1 R8.2 R9.2 | length 3.1
  Top Layer w0.203: Q1.1 35.872,3.832 R8.2
NetU1_A6: U1.A6 U1.B6 U2.7 | length 25.5
  Top Layer w0.178: U2.7 29.973,1.498 32.11,-0.639 U1.A6 32.11,-18.265 32.097,-18.277 32.097,-19.092 32.266,-19.262 33.026,-19.262 33.13,-19.157 33.13,-18.277 33.11,-18.256 U1.B6
NetU1_A7: U1.A7 U1.B7 U2.8 | length 24.7
  Top Layer w0.178: U2.8 30.475,2.226 30.475,1.758 32.61,-0.377 U1.A7 32.61,-18.487 v1(32.614,-18.491) ; v1(31.217,-18.593) 31.61,-18.2 U1.B7
  Bottom Layer w0.178: v1(31.217,-18.593) 31.278,-18.531 31.486,-18.531 31.526,-18.491 v1(32.614,-18.491)
P00_1: J3.3 J3.4 J4.2 J5.4 | length 68.6
  Top Layer w0.508: J4.2 -15.57,35.357 -11.709,31.496 -11.709,-2.21 J5.4
  Bottom Layer w0.508: J4.2 -0.043,35.357 J3.3 J3.4
P01_1: J3.7 J3.8 J4.4 J5.2 | length 56.8
  Top Layer w0.508: J4.4 -15.545,30.277 -13.767,28.499 -13.767,0.733 J5.2
  Bottom Layer w0.508: J4.4 -0.043,30.277 J3.7 J3.8
P02_1: J1.7 J1.8 J2.9 | length 17.6
  Top Layer w0.508: J2.9@41.327,30.318 41.54,30.531 J2.9
  Bottom Layer w0.508: J1.7 J1.8 41.327,30.318 41.54,30.531 J2.9
P03_1: C9.2 J3.1 J3.2 J4.1 J5.5 K2.1 K2.2 R7.1 | length 91.8
  Top Layer w0.508: J4.1 -12.04,37.897 -10.084,35.941 -10.084,-3.084 -12.242,-5.242 J5.5 -16.779,-9.79 -14.998,-11.571 C9.2 -9.502,-11.571 -9.431,-11.642 K2.2 K2.1 -11.22,-16.119 -11.235,-16.134 -11.518,-16.134 -11.564,-16.18 R7.1
  Bottom Layer w0.508: J4.1 -0.043,37.897 J3.1 J3.2
P04_1: J1.9 J1.10 J2.8 J17.1 | length 60.3
  Top Layer w0.508: J17.1 4.724,20.015 12.487,27.778 J1.9
  Bottom Layer w0.508: J1.9 J1.10 27.684,27.778 27.897,27.991 J2.8
P05_1: J1.11 J1.12 J2.7 J9.1 | length 51.9
  Bottom Layer w0.254: J1.11 24.669,25.032 23.99,25.032 21.463,22.504 21.463,2.261 23.393,0.33 23.393,-2.388 23.978,-2.972 25.679,-2.972 26.986,-1.666 J9.1
  Bottom Layer w0.508: J1.11 J1.12 27.684,25.238 27.897,25.451 J2.7
P06_1: J1.13 J1.14 J2.6 J8.1 | length 43.3
  Bottom Layer w0.254: J8.1 24.663,0.432 22.479,2.616 22.479,20.32 24.857,22.698 J1.13 J1.14
  Bottom Layer w0.508: J1.14 41.015,22.698 41.038,22.721 41.619,22.721 J2.6
P07_1: C1.2 J1.15 J1.16 J2.5 K1.1 K1.2 | length 72.1
  Top Layer w0.508: K1.2 K1.1 2.943,-11.719 3.023,-11.799 C1.2 3.073,-11.799 3.119,-11.753 3.119,-11.728 6.756,-8.091 6.756,15.494 11.42,20.158 J1.15
  Bottom Layer w0.508: J1.15 J1.16 27.684,20.158 27.897,20.371 J2.5
P10_1: J1.17 J1.18 J2.4 R8.1 | length 32.1
  Top Layer w0.508: R8.1 37.871,6.426 38.659,7.214 38.659,16.205 40.284,17.831 J2.4
  Bottom Layer w0.508: J1.17 J1.18 41.327,17.618 41.54,17.831 J2.4
P11_1: IR1.1 J1.19 J1.20 J2.3 R4.2 | length 39
  Top Layer w0.508: R4.2 39.834,-0.603 40.391,-0.045 40.691,-0.045 ; v1(40.716,0.483) 40.716,-0.02 40.691,-0.045 ; J2.3@41.327,15.078 41.54,15.291 J2.3 ; IR1.1 40.691,-0.045
  Bottom Layer w0.508: J1.19 J1.20 41.015,15.078 41.038,15.101 J2.3@41.619,15.101 ; v1(40.716,0.483) 40.716,6.604 40.742,6.629 39.7,7.671 39.7,13.183 J2.3@41.619,15.101 ; J2.3 J2.3@41.619,15.101
P12_1: J3.23 J3.24 J4.12 | length 20.2
  Bottom Layer w0.508: J4.12 -0.043,9.957 J3.23 J3.24
P13_1: J1.21 J1.22 J13.2 | length 35
  Top Layer w0.254: J13.2 9.347,7.137 14.748,12.538 J1.21 J1.22
P14_1: J1.23 J1.24 J10.2 | length 30.7
  Top Layer w0.254: J10.2 11.887,5.969 15.916,9.998 J1.23 J1.24
P15_1: J3.21 J3.22 J4.11 | length 20.2
  Bottom Layer w0.508: J4.11 -17.584,12.54 J3.21 J3.22
P16_DIP_1: J3.19 J3.20 J4.10 | length 20.2
  Bottom Layer w0.508: J4.10 -17.584,15.08 J3.19 J3.20
P17_DIP_1: J3.17 J3.18 J4.9 | length 20.2
  Bottom Layer w0.508: J4.9 2.497,17.577 J3.18
P20_1: J3.15 J3.16 J4.8 | length 20.2
  Bottom Layer w0.508: J4.8 -17.584,20.16 J3.15 J3.16
P21_1: J3.13 J3.14 J4.7 | length 20.2
  Bottom Layer w0.508: J4.7 -17.584,22.7 J3.13 J3.14
P22_1: J3.11 J3.12 J4.6 | length 20.2
  Bottom Layer w0.508: J4.6 -0.043,25.197 J3.11 J3.12
VBAT_1: J1.3 J1.4 J2.11 J3.9 J3.10 J4.5 J5.1 J15.2 R7.2 | length 156.1
  Top Layer w0.508: J4.5 -17.473,27.582 -16.66,27.582 -15.392,26.314 -15.392,8.547 -16.891,7.049 -16.891,0.312 J5.1 -17.179,-0.18 -17.985,-0.18 -18.872,-1.067 -18.872,-11.836 -14.583,-16.125 -13.113,-16.125 -13.067,-16.172 -12.447,-16.172 R7.2 ; J3.10 6.444,27.78 14.062,35.398 J1.3
  Bottom Layer w0.508: J4.5 -17.584,27.78 J3.9 J3.10 ; J15.2 17.729,0.229 17.729,30.683 22.444,35.398 J1.3 J1.4 41.327,35.398 41.54,35.611 J2.11
VBUS: J6.1 J6.2 J6.3 J6.4 SW1.2 SW1.5 U1.A4/B9 U1.A9/B4 U4.A4/B9 U4.A9/B4 | length 80.3
  Top Layer w0.254: U4.A4/B9 8.742,-17.032 8.742,-17.706 8.766,-17.73 8.766,-18.164 10.262,-19.66 12.167,-19.66 13.286,-18.54 13.286,-17.73 13.31,-17.706 13.31,-17.032 U4.A9/B4 ; 29.515,-20.117 29.515,-20.092 29.909,-19.698 ; 29.896,-20.117 30.099,-19.913 ; U1.A4/B9 30.076,-17.185 30.076,-17.858 30.099,-17.882 30.099,-19.254 ; 30.963,-20.117 30.543,-19.698 ; J6.3@40.869,-8.788 J6.4 ; 29.909,-19.698 29.909,-19.723 30.099,-19.913 ; 29.909,-19.698 30.099,-19.507 ; 29.909,-19.698 30.099,-19.698 ; 30.099,-19.913 30.269,-19.913 ; 30.099,-19.913 30.213,-19.799 ; 30.099,-19.913 30.099,-19.698 ; 30.099,-19.698 30.099,-19.584 ; 30.099,-19.698 30.213,-19.698 ; 30.099,-19.584 30.213,-19.698 ; 30.099,-19.584 30.099,-19.507 ; 30.099,-19.507 30.099,-19.254 ; 30.099,-19.254 30.543,-19.698 ; 30.213,-19.799 30.213,-19.698 ; 30.213,-19.799 30.213,-19.857 30.269,-19.913 ; 30.213,-19.799 30.315,-19.698 ; 30.213,-19.698 30.315,-19.698 ; 30.269,-19.913 30.473,-20.117 30.543,-20.046 30.543,-19.698 ; 30.269,-19.913 30.328,-19.913 30.543,-19.698 ; 30.315,-19.698 30.543,-19.698
  Top Layer w0.508: U4.A9/B4 13.426,-15.106 13.723,-14.808 15.697,-14.808 16.942,-16.053 16.942,-17.704 19.355,-20.117 21.177,-20.117 ; SW1.5 21.533,-20.625 ; SW1.2 21.533,-19.761 ; U1.A9/B4 34.806,-17.023 34.806,-16.507 34.828,-16.485 34.828,-16.315 35.081,-16.062 35.484,-16.062 ; 34.76,-16.485 34.76,-15.621 ; J6.1 42.951,-6.248 43.18,-6.477 J6.4 ; J6.3@40.869,-8.788 J6.3 38.633,-8.788 34.76,-12.662 34.76,-15.621 ; 21.177,-20.117 21.177,-20.269 21.533,-20.625 ; 21.177,-20.117 21.533,-20.117 ; 21.177,-20.117 21.533,-19.761 ; 21.533,-20.625 21.533,-20.472 ; 21.533,-20.472 21.533,-20.117 ; 21.533,-20.472 21.888,-20.117 ; 21.533,-20.117 21.888,-20.117 ; 21.533,-20.117 21.533,-19.761 ; 21.533,-19.761 21.888,-20.117 ; 21.888,-20.117 29.515,-20.117 29.896,-20.117 30.473,-20.117 30.963,-20.117 33.553,-20.117 33.579,-20.091 37.599,-20.091 37.897,-19.794 37.897,-16.359 37.599,-16.062 35.484,-16.062 ; 34.76,-15.621 35.043,-15.621 35.484,-16.062
VBUS_3V_1: J1.1 J1.2 J2.12 J16.2 | length 64.7
  Bottom Layer w0.508: J16.2 14.656,0.762 14.656,32.639 19.955,37.938 J1.1 J1.2 41.327,37.938 41.54,38.151 J2.12
VBUS_5V_1: J1.5 J1.6 J2.10 J14.2 | length 55.4
  Bottom Layer w0.508: J14.2 19.863,0.635 19.863,29.312 23.409,32.858 J1.5 J1.6 41.327,32.858 41.54,33.071 J2.10
pads on no net: J2.1 J2.2 SW1.1 SW1.4 U1. U1.A5 U1.A8 U1.B5 U1.B8 U2.10 U2.11 U2.12 U2.13 U2.14 U2.15 U2.16 U4. U4.A5 U4.A8 U4.B5 U4.B8

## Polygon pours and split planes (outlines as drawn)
GND on Bottom Layer "GND_L02_P001" (solid, remove dead copper, pour order 1): -16.154,-23.622 40.68,-23.622 40.756,-23.546 45.11,-23.546 45.11,52.781 44.247,53.645 -19.558,53.645 -21.006,52.197 -21.006,-22.022 -19.431,-23.597 -17.323,-23.597
GND on Top Layer "GND_L01_P000" (solid, remove dead copper, pour order 0): -19.4,52.762 -18.319,52.762 43.504,52.762 45.085,51.181 45.085,-20.955 42.113,-23.927 41.808,-23.622 -18.466,-23.622 -20.93,-21.158 -20.93,51.398

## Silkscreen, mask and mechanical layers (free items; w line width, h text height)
Top Overlay:
  lines w0.1: 43.502,-2.039 44.286,-2.039 ccw(c44.286,-1.658) 44.667,-1.658 44.667,-0.87 cw(c44.671,-0.87) 44.671,-0.867 ccw(c44.347,-0.867) 44.347,-0.543 43.51,-0.543 ; 43.716,3.81 44.501,3.81 ccw(c44.501,4.191) 44.882,4.191 44.882,4.979 cw(c44.886,4.979) 44.886,4.982 ccw(c44.562,4.982) 44.562,5.306 43.725,5.306
  lines w0.203: 30.053,6.116 30.053,6.802
  text "PN271_Kit_Base_V1.1" at -12.395,48.158 h3.05
  text "260130" at -12.234,45.497 h2.54
  text "VBUS_3V" at 33.604,37.376 h1.65
  text "P03" at -14.884,37.307 h1.65
  text "P00" at -14.834,35.04 h1.65
  text "VBAT" at 35.966,34.9 h1.65
  text "GND" at -14.935,32.557 h1.65
  text "VBUS_5V" at 33.325,32.423 h1.65
  text "P01" at -14.859,29.865 h1.65
  text "P02" at 36.373,29.712 h1.65
  text "P04" at 36.297,27.401 h1.65
  text "VBAT" at -15.24,27.381 h1.65
  text "P22" at -14.808,24.841 h1.65
  text "P05" at 36.424,24.658 h1.65
  text "P06" at 36.474,22.27 h1.65
  text "P21" at -14.834,22.2 h1.65
  text "P20" at -14.834,19.705 h1.65
  text "P07" at 36.443,19.451 h1.65
  text "P17" at -14.834,17.253 h1.65
  text "P10" at 36.449,17.012 h1.65
  text "P16" at -14.834,14.809 h1.65
  text "P11" at 36.443,14.199 h1.65
  text "P13" at 29.547,12.149 h1.65
  text "P15" at -14.834,12.085 h1.65
  text "NC" at 36.449,11.804 h1.65
  text "P14" at 29.572,9.564 h1.65
  text "P12" at -14.834,9.524 h1.65
  text "NC" at 36.443,9.188 h1.65
  text "VBAT" at 19.939,2.007 h1.5 r90
  text "VBUS_3V" at 17.058,1.829 h1.5 r90
  text "VBUS_5V" at 22.443,1.676 h1.5 r90
  text "UART" at 24.105,1.313 h1.5
  text "VBAT" at -14.021,-0.102 h1.65
  text "DIO" at -10.338,-2.825 h1.65
  text "P01" at -13.792,-2.876 h1.65
  text "USB" at 9.423,-3.886 h1.52
  text "GND" at -13.894,-5.289 h1.65
  text "5V" at 21.361,-6.401 h1.4
  text "3V3" at 18.596,-6.57 h1.4
  text "3V3" at 15.875,-6.682 h1.4
  text "P00" at -13.64,-7.976 h1.52
  text "CLK" at -10.439,-8.033 h1.65
  text "VBUS" at 38.156,-9.169 h1.65 r90
  text "RST" at -10.262,-10.216 h1.65
  text "P03" at -13.741,-10.262 h1.52
  text "GND" at 38.791,-15.113 h1.65 r90
  text "UART" at 29.82,-15.189 h2
  text "RST" at -4.725,-15.799 h2.16 r90
  text "USB" at 5.158,-21.387 h2 r90
  text "总开关" at 26.543,-22.123 h2 r90
Mechanical 1:
  circle w0.127: c-17.069,49.403 r1.558
  circle w0.127: c41.605,49.86 r1.558
  circle w0.127: c41.478,-19.761 r1.558
  circle w0.127: c-15.773,-18.974 r1.558
  lines w0.508: 40.488,-23.597 ccw(c41.11,-19.621) 45.085,-20.244 45.085,-19.122 45.085,50.521 ccw(c42.418,50.521) 42.418,53.188 -19.025,52.857 ccw(c-18.809,50.787) -20.879,50.571 -20.879,-19.254 -20.879,-20.244 ccw(c-16.827,-19.571) -16.154,-23.622 40.792,-23.622
Mechanical 15:
  lines w1: -5.359,8.128 -5.102,51.127 31.801,51.054 ; -5.222,8.018 31.775,7.595 32.033,50.594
